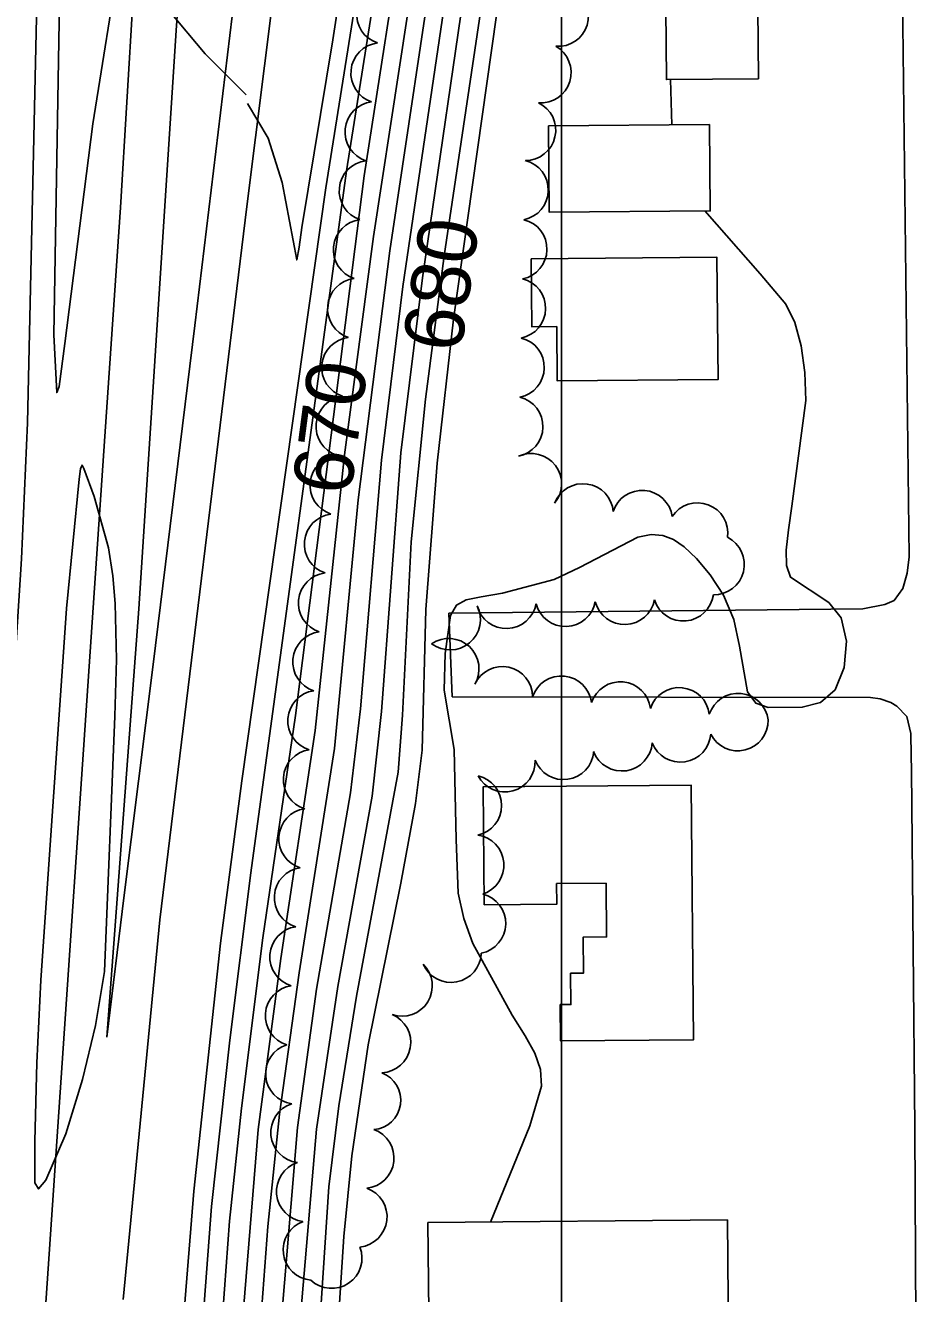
# Model space of a CAD drawing. Extents: x 79600 to 91800, y 75600 to 84400.
# Drawn here: x 86518.8 to 86821.1, y 79087.1 to 79515.8 of the extents above; entities that cross this region are included whole.
import ezdxf

# ---------------------------------------------------------------- set-up
doc = ezdxf.new("R2010")
doc.units = 0
for name, color, linetype in [('080-085$0$TI_BORDER', 7, 'Continuous'), ('080-090$0$BLDG', 7, 'Continuous'), ('080-090$0$INDEX', 7, 'Continuous'), ('080-090$0$INDXLBL', 7, 'Continuous'), ('080-090$0$INTER', 7, 'Continuous'), ('080-090$0$INTERSTATE', 7, 'Continuous'), ('080-090$0$ROAD', 7, 'Continuous'), ('080-090$0$TREES', 7, 'Continuous')]:
    doc.layers.add(name, color=color, linetype=linetype)

msp = doc.modelspace()

# ---------------------------------------------------------------- linework, layer by layer
at = {"layer": '080-085$0$TI_BORDER'}
msp.add_lwpolyline([(79700, 80300), (86700, 80300), (86700, 75700), (79700, 75700)], close=True, dxfattribs=at)
at = {"layer": '080-090$0$BLDG'}
for points in [[(86734.92, 79557.7), (86735.45, 79497.53), (86766.56, 79497.8), (86766.04, 79557.98)], [(86695.64, 79481.82), (86695.89, 79452.65), (86750.28, 79453.12), (86750.03, 79482.3)], [(86689.74, 79436.91), (86689.94, 79413.97), (86698.41, 79414.04), (86698.57, 79395.65), (86752.93, 79396.13), (86752.57, 79437.46)], [(86673.85, 79218.54), (86698.39, 79218.76), (86698.33, 79225.74), (86715.09, 79225.88), (86715.25, 79207.71), (86707.34, 79207.64), (86707.44, 79195.46), (86703.08, 79195.42), (86703.17, 79184.86), (86699.58, 79184.83), (86699.69, 79172.54), (86744.6, 79172.93), (86743.85, 79259.01), (86673.5, 79258.4)], [(86655.25, 79070.71), (86756.42, 79071.59), (86756.07, 79112.06), (86654.89, 79111.18)]]:
    msp.add_lwpolyline(points, close=True, dxfattribs=at)
at = {"layer": '080-090$0$INDEX'}
for points in [[(86794.84, 80000), (86783.11, 79983.55), (86767.05, 79957.92), (86758.01, 79940.3), (86743.03, 79904.75), (86719.25, 79841.72), (86707.01, 79806.04), (86679.46, 79703.71), (86668.02, 79658.6), (86660.02, 79622.49), (86647.85, 79558.56), (86633.32, 79464.99), (86610.07, 79282.52), (86599.03, 79207.39), (86591.82, 79149.83), (86587.83, 79111.6), (86581.57, 79027.31), (86578.33, 78959.69), (86577.33, 78815.09), (86577.23, 78795.59), (86573.92, 78757.92)], [(86800.04, 79977.16), (86787.89, 79956.36), (86780.56, 79938.68), (86749.38, 79836.84), (86697.53, 79644.09), (86690.23, 79616.74), (86680.01, 79569.49), (86660.4, 79437.95), (86654.03, 79389.47), (86649.19, 79341.29), (86646.22, 79282.72), (86644.79, 79263.44), (86630.75, 79187.68), (86624.79, 79150.58), (86621.37, 79123.29), (86616.84, 79054.9), (86610.12, 78988.14), (86607.68, 78959.03), (86606.12, 78922.22), (86607.62, 78817.75), (86607.87, 78808.44), (86607.67, 78799.18), (86606.63, 78790.02), (86598.08, 78758.37)]]:
    msp.add_lwpolyline(points, dxfattribs=at)
at = {"layer": '080-090$0$INTER'}
msp.add_line((86736.81, 79497.54), (86737.27, 79482.19), dxfattribs=at)
for points in [[(86785.85, 80000), (86772.33, 79981.48), (86762.36, 79966.03), (86752.85, 79949.06), (86736.17, 79914.45), (86721.14, 79879.02), (86703.54, 79833.6), (86690.47, 79796.23), (86666.03, 79704.25), (86657.03, 79668.46), (86645.97, 79613.62), (86635.58, 79556.42), (86620.34, 79460.97), (86591.99, 79260.49), (86584.81, 79205.6), (86575.71, 79121.74), (86570.67, 79058.78), (86567.36, 78980.62), (86564.6, 78757.75)], [(86790.46, 80000), (86775.69, 79979.74), (86761.13, 79955.97), (86748.7, 79930.22), (86733.83, 79895.73), (86716.45, 79850.83), (86703.05, 79813.95), (86694.22, 79785.97), (86672.55, 79703.18), (86663.19, 79666.37), (86654.84, 79627.73), (86642.47, 79561.99), (86627.36, 79466.66), (86594.98, 79229.34), (86587.9, 79172.84), (86581.76, 79116.56), (86575.97, 79040.28), (86572.27, 78953.52), (86571.26, 78815.88), (86569.34, 78757.84)], [(86799.91, 80000), (86785.98, 79981.15), (86775.44, 79964.65), (86765.95, 79947.11), (86754.38, 79919.95), (86734.14, 79865.32), (86721.46, 79829.9), (86710.03, 79793.54), (86685.27, 79700), (86671.18, 79644.22), (86661.04, 79596.02), (86653.77, 79557.73), (86636.48, 79444.47), (86626.68, 79370.64), (86616.7, 79277.49), (86605.13, 79200.38), (86597.49, 79142.66), (86588.9, 79037.78), (86585.29, 78979.02), (86583.25, 78931.49), (86583.34, 78816.29), (86583.31, 78796.92), (86578.77, 78758.01)], [(86781, 80000), (86770.92, 79986.64), (86752.13, 79956.39), (86742.89, 79939.68), (86726.3, 79904.77), (86710.96, 79869.03), (86693.26, 79823.74), (86683.98, 79797.02), (86664.49, 79724.1), (86654.93, 79687.34), (86646.68, 79649.59), (86630.94, 79564.31), (86622.75, 79510.92), (86612.24, 79447.53), (86611.3, 79440.89), (86610.52, 79436.56), (86605.58, 79462.72), (86600.86, 79477.72), (86593.83, 79489.4)], [(86800.15, 79994.9), (86788.5, 79978.41), (86778.62, 79962.52), (86769.75, 79945.46), (86759.1, 79918.69), (86736.43, 79854.58), (86724.07, 79817.83), (86693.17, 79704.08), (86676.27, 79637.8), (86667.84, 79599.72), (86658.8, 79551.99), (86641.97, 79439.63), (86631.24, 79355.51), (86623.29, 79271.4), (86611.3, 79195.53), (86604.7, 79147.77), (86600.71, 79109.86), (86594.35, 79024.24), (86590.04, 78957.56), (86588.82, 78919.68), (86589.16, 78833.11), (86589.55, 78805.07), (86588.64, 78786.49), (86583.52, 78758.1)], [(86800.26, 79988.38), (86795.22, 79981.63), (86785.33, 79966.12), (86776.26, 79949.31), (86768.82, 79931.84), (86738.24, 79841.66), (86726.87, 79804.96), (86684.62, 79644.95), (86677.8, 79617.25), (86669.85, 79579.4), (86663.15, 79541.36), (86646.41, 79427.52), (86639.13, 79368.82), (86632.03, 79284.84), (86628.74, 79256.41), (86617.22, 79190.07), (86610.73, 79143.3), (86599.75, 79011.42), (86595.65, 78953.14), (86594.59, 78914.32), (86595.17, 78828.2), (86595.55, 78809.8), (86594.84, 78791.85), (86588.84, 78758.2)], [(86793.29, 79971.93), (86783.86, 79955.66), (86776.17, 79938.96), (86747.15, 79849.66), (86733.2, 79803.8), (86691.64, 79646.94), (86684.36, 79618.64), (86676.24, 79580.77), (86669.35, 79542.81), (86653.04, 79430.48), (86645.76, 79371.29), (86639.19, 79283.96), (86636.06, 79255.3), (86624.37, 79190.92), (86617.24, 79142.72), (86604.75, 78996.34), (86601.69, 78957.57), (86600.49, 78928.14), (86601.53, 78812.54), (86600.4, 78793.66), (86594.77, 78758.31)], [(86550.97, 79541.02), (86541.62, 79482.56), (86532.11, 79408.31), (86530.18, 79393.82), (86529.4, 79391.71), (86528.44, 79411.28), (86531.25, 79576.88)], [(86476.85, 78756.13), (86481.69, 78768.42), (86486.16, 78782.8), (86489.97, 78800.08), (86493.43, 78828.29), (86498.63, 78942.09), (86499.6, 78971.48), (86498.29, 79028.94), (86499.11, 79065.82), (86506.03, 79156.31), (86517.48, 79335.46), (86519.47, 79381.53), (86523.84, 79574.39)], [(86601.82, 78758.44), (86606.26, 78768.56), (86609.2, 78776.31), (86611.75, 78785.2), (86613.25, 78794.45), (86612.12, 78888.51), (86612.21, 78934.2), (86614.77, 78972.7), (86622.11, 79040.64), (86626.39, 79106.48), (86629.16, 79133.73), (86634.65, 79171.25), (86645.73, 79225.91), (86650.7, 79252.87), (86652.94, 79270.83), (86654.19, 79318.36), (86658.04, 79367.8), (86663.46, 79416.58), (86679.61, 79530.52)], [(86593.39, 79492.36), (86579.62, 79506.26), (86567.26, 79520.83)], [(86748.5, 79453.11), (86767.2, 79431.89), (86775.83, 79421.55), (86778.89, 79415.37), (86781.03, 79407.53), (86782.24, 79398.5), (86782.55, 79389.05), (86777.91, 79353.3), (86776.7, 79345.31), (86775.99, 79338.48), (86776.09, 79333.22), (86777.41, 79329.3), (86790.35, 79320.79), (86794.51, 79315.61), (86796.29, 79307.66), (86795.59, 79298.73), (86792.56, 79291.24), (86787.53, 79286.98), (86781.39, 79285.33), (86769.86, 79285.3), (86765.69, 79286.78), (86762.87, 79290.56), (86760.21, 79305.95), (86758.29, 79315.01), (86754.8, 79323.2), (86750.28, 79330.14), (86745.62, 79335.62), (86741.52, 79339.53), (86737.84, 79342.05), (86734.23, 79343.4), (86730.35, 79343.73), (86725.86, 79342.88), (86706.08, 79332.55), (86697.58, 79328.57), (86680.08, 79323.9), (86672.89, 79322.7), (86667.78, 79321.67), (86664.48, 79319.89), (86662.47, 79316.39), (86660.68, 79303.52), (86660.34, 79291.18), (86663.73, 79271.05), (86664.36, 79240.62), (86665.1, 79222.56), (86667, 79213.89), (86670, 79205.48), (86683.37, 79181.3), (86687.7, 79174.34), (86690.99, 79168.4), (86692.94, 79162.95), (86693.29, 79157.29), (86689.33, 79143.89), (86676.03, 79111.36)]]:
    msp.add_lwpolyline(points, dxfattribs=at)
msp.add_lwpolyline([(86537, 79362.47), (86532.71, 79318.78), (86524.08, 79193.07), (86522.73, 79165.2), (86522.01, 79138.66), (86522.06, 79124.6), (86523.26, 79122.52), (86525.74, 79125.54), (86532.46, 79141.19), (86538.13, 79159.49), (86542.52, 79177.74), (86545.57, 79196.02), (86549.09, 79282.3), (86549.58, 79301.44), (86549.16, 79320.38), (86548.35, 79329.79), (86546.87, 79339.2), (86542.1, 79356.63), (86538.62, 79366.01), (86537.98, 79367.21), (86537.42, 79365.9)], close=True, dxfattribs=at)
at = {"layer": '080-090$0$INTERSTATE'}
for p, q in [((86614.71, 79623.35), (86593.7, 79454.59)), ((86576.28, 79618.4), (86569.83, 79514.09)), ((86550.91, 79454.28), (86557.22, 79558.6)), ((86576.05, 79414.42), (86592.71, 79552.1)), ((86569.83, 79514.09), (86557.13, 79318.61)), ((86545.19, 79370.31), (86550.91, 79454.28)), ((86593.7, 79454.59), (86564.24, 79213.53)), ((86561.97, 79299.84), (86576.05, 79414.42)), ((86524.78, 79069.56), (86545.19, 79370.31)), ((86557.13, 79318.61), (86546.32, 79173.78)), ((86552.03, 79220.92), (86561.97, 79299.84)), ((86546.32, 79173.78), (86552.03, 79220.92)), ((86564.24, 79213.53), (86551.88, 79085.21))]:
    msp.add_line(p, q, dxfattribs=at)
at = {"layer": '080-090$0$ROAD'}
for p, q in [((86810.95, 79903.39), (86817.47, 79336.21)), ((86817.47, 79336.21), (86816.83, 79330.68)), ((86816.83, 79330.68), (86815.37, 79325.44)), ((86815.37, 79325.44), (86812.4, 79321.47)), ((86809.33, 79320.13), (86801.83, 79318.59)), ((86812.4, 79321.47), (86809.33, 79320.13)), ((86801.83, 79318.59), (86661.94, 79317.14)), ((86661.94, 79317.14), (86663.03, 79288.87)), ((86663.03, 79288.87), (86804.42, 79288.64)), ((86804.42, 79288.64), (86807.73, 79288.17)), ((86807.73, 79288.17), (86811.31, 79287.01)), ((86811.31, 79287.01), (86813.37, 79285.73)), ((86813.37, 79285.73), (86816.78, 79282.22)), ((86816.78, 79282.22), (86818.08, 79276.52)), ((86818.08, 79276.52), (86818.24, 79268.9)), ((86818.24, 79268.9), (86818.3, 79264.05)), ((86818.3, 79264.05), (86819.49, 79143.28)), ((86819.49, 79143.28), (86821.06, 78776.83))]:
    msp.add_line(p, q, dxfattribs=at)
at = {"layer": '080-090$0$TREES'}
for centre, radius, start, end in [((86641.04, 79519.61), 10.25, 97.0321, 251.6713), ((86698.9, 79518.97), 10.25, 265.5444, 60.1836), ((86639.07, 79499.7), 10.25, 97.0321, 251.6713), ((86693.01, 79499.86), 10.25, 265.5444, 60.1836), ((86637.1, 79479.8), 10.25, 97.0321, 251.6713), ((86687.81, 79480.39), 10.25, 269.9092, 64.5485), ((86635.13, 79459.9), 10.25, 97.0321, 251.6713), ((86685.31, 79460.19), 10.25, 281.3767, 76.0159), ((86633.16, 79439.99), 10.25, 97.0321, 251.6713), ((86684.86, 79440.2), 10.25, 281.3767, 76.0159), ((86631.19, 79420.09), 10.25, 97.0321, 251.6713), ((86684.4, 79420.2), 10.25, 281.3767, 76.0159), ((86629.22, 79400.19), 10.25, 97.0321, 251.6713), ((86683.95, 79400.21), 10.25, 281.3767, 76.0159), ((86627.26, 79380.29), 10.25, 97.0321, 251.6713), ((86683.49, 79380.21), 10.25, 281.3767, 76.0159), ((86689.82, 79360.86), 10.25, 320.1858, 114.8251), ((86625.29, 79360.38), 10.25, 97.0321, 251.6713), ((86707.28, 79350.66), 10.25, 4.5974, 159.2366), ((86727.27, 79348.42), 10.25, 7.9339, 162.5731), ((86745.99, 79344.2), 10.25, 352.0714, 146.7106), ((86623.32, 79340.48), 10.25, 97.0321, 251.6713), ((86751.57, 79333.62), 10.25, 268.8321, 63.4713), ((86621.35, 79320.58), 10.25, 97.0321, 251.6713), ((86662.35, 79314.97), 10.25, 232.5546, 27.1939), ((86681.39, 79322.23), 10.25, 194.5706, 349.2098), ((86701.38, 79322.89), 10.25, 194.5706, 349.2098), ((86721.37, 79323.55), 10.25, 194.5706, 349.2098), ((86741.2, 79324.74), 10.25, 197.6785, 352.3177), ((86619.43, 79300.68), 10.25, 97.3227, 251.962), ((86661.88, 79298.35), 10.25, 329.5746, 124.2138), ((86680.01, 79288.83), 10.25, 0.3483, 154.9875), ((86699.99, 79285.67), 10.25, 7.0554, 161.6947), ((86719.89, 79283.71), 10.25, 7.0554, 161.6947), ((86617.75, 79280.79), 10.25, 98.33, 252.9692), ((86739.8, 79281.75), 10.25, 7.0554, 161.6947), ((86759.7, 79279.79), 10.25, 7.0554, 161.6947), ((86759.62, 79280.86), 10.25, 206.4075, 1.0467), ((86720.44, 79274.05), 10.25, 201.2396, 355.8788), ((86740.22, 79277.03), 10.25, 201.2629, 355.9021), ((86616.23, 79260.85), 10.25, 98.33, 252.9692), ((86700.67, 79271.14), 10.25, 200.9059, 355.5452), ((86680.86, 79266.98), 10.25, 208.1336, 2.7728), ((86669.52, 79252.16), 10.25, 282.3934, 77.0327), ((86614.71, 79240.91), 10.25, 98.33, 252.9692), ((86670.32, 79232), 10.25, 287.5103, 82.1496), ((86613.19, 79220.97), 10.25, 98.33, 252.9692), ((86670.91, 79212.28), 10.25, 281.2789, 75.9181), ((86611.68, 79201.02), 10.25, 98.33, 252.9692), ((86662.67, 79202.57), 10.25, 203.4282, 358.0674), ((86646.1, 79191.17), 10.25, 251.0003, 45.6395), ((86610.16, 79181.08), 10.25, 98.33, 252.9692), ((86638.82, 79172.02), 10.25, 272.7219, 67.3611), ((86610.24, 79161.5), 10.25, 107.4863, 262.1255), ((86635.77, 79152.51), 9.92, 274.4947, 69.134), ((86612.02, 79141.61), 10.25, 108.1402, 262.7795), ((86633.14, 79132.96), 10.25, 275.9591, 70.5984), ((86613.93, 79121.7), 10.25, 108.1402, 262.7795), ((86630.8, 79113.1), 10.25, 275.9591, 70.5984), ((86616.2, 79101.92), 10.25, 110.3014, 264.9406), ((86622.32, 79099.17), 10.25, 226.7106, 21.3499)]:
    msp.add_arc(centre, radius, start, end, dxfattribs=at)

# ---------------------------------------------------------------- texts
at = {"layer": '080-090$0$INDXLBL'}
for s, rotation, p in [('680', 81.954, (86666.01, 79404.8)), ('670', 82.5119, (86628.72, 79356.59))]:
    msp.add_text(s, height=20, rotation=rotation, dxfattribs=at).set_placement(p)

doc.saveas('drawing.dxf')
